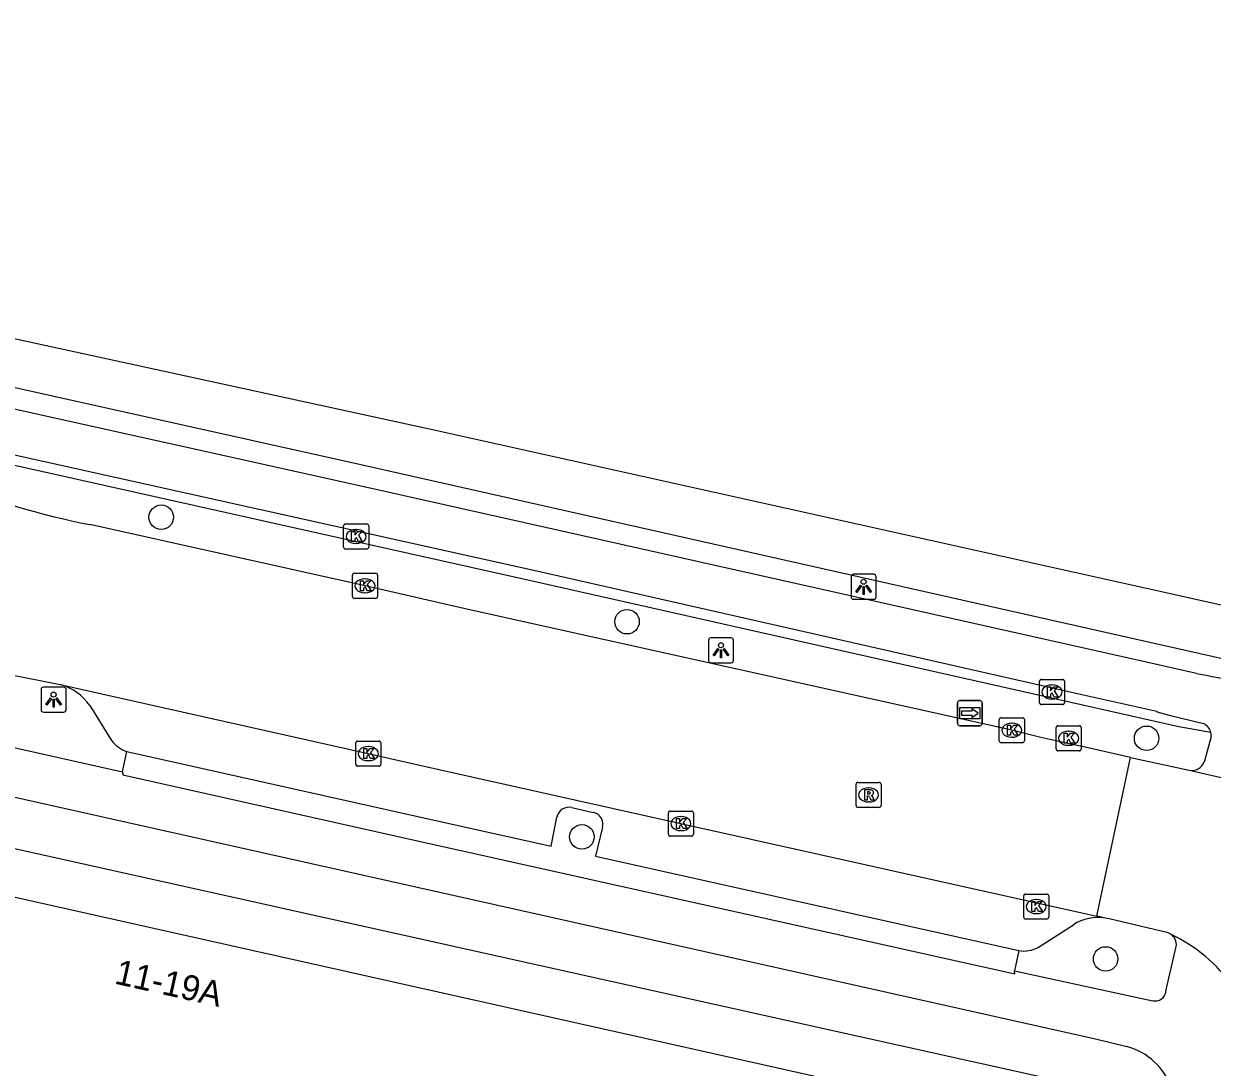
# Model space of a CAD drawing. Extents: x 161771 to 163125, y 382479 to 383177.
# Drawn here: x 162196.88 to 162244.33, y 383044.65 to 383086.29 of the extents above; entities that cross this region are included whole.
import ezdxf

# ---------------------------------------------------------------- set-up
doc = ezdxf.new("R2010")
doc.units = 0
for name, color, linetype in [('IMGEO_Boom', 7, 'Continuous'), ('IMGEO_Fietspad_gesloten', 7, 'Continuous'), ('IMGEO_Haag', 7, 'Continuous'), ('IMGEO_Kolk', 7, 'Continuous'), ('IMGEO_Lichtpunt', 7, 'Continuous'), ('IMGEO_Pand', 7, 'Continuous'), ('IMGEO_Pand_nummerreeks', 7, 'Continuous'), ('IMGEO_Parkeervlak_open', 7, 'Continuous'), ('IMGEO_Rijbaan_lokaal_gesloten', 7, 'Continuous'), ('IMGEO_Rijbaan_lokaal_open', 7, 'Continuous'), ('IMGEO_Rioolput', 7, 'Continuous'), ('IMGEO_Voetpad_open', 7, 'Continuous'), ('IMGEO_Wegwijzer', 7, 'Continuous')]:
    doc.layers.add(name, color=color, linetype=linetype)

msp = doc.modelspace()

# ---------------------------------------------------------------- linework, layer by layer
at = {"layer": 'IMGEO_Boom'}
for centre in [(162202.368, 383066.6), (162220.965, 383062.428), (162241.709, 383057.778), (162219.163, 383053.844), (162240.073, 383048.972)]:
    msp.add_circle(centre, 0.489, dxfattribs=at)
at = {"layer": 'IMGEO_Fietspad_gesloten'}
for points in [[(162243.707, 383060.368), (162241.754, 383060.795), (162210.53, 383067.797), (162194.926, 383071.263), (162193.872, 383071.53)], [(162195.294, 383069.358), (162217.239, 383064.484), (162239.123, 383059.53), (162242.124, 383058.863), (162242.112, 383058.831), (162242.616, 383058.703), (162243.975, 383058.365)], [(162170.379, 383061.276), (162174.223, 383060.417), (162179.202, 383059.305), (162239.663, 383045.787), (162240.925, 383045.477)], [(162179.884, 383061.009), (162180.126, 383061.066), (162200.828, 383056.444)], [(162244.014, 383056.841), (162244.286, 383057.805)], [(162200.828, 383056.444), (162200.835, 383056.323), (162212.596, 383053.683), (162236.448, 383048.373), (162236.439, 383048.504)], [(162242.483, 383047.687), (162242.895, 383049.474)], [(162236.439, 383048.504), (162240.976, 383047.517), (162241.952, 383047.305)]]:
    msp.add_lwpolyline(points, dxfattribs=at)
for centre, radius, start, end in [((162252.874, 383104.047), 44.631, 258.1478, 264.5942), ((162243.759, 383057.878), 0.532, 13.4374, 66.0806), ((162243.776, 383057.88), 0.516, 351.5944, 13.6371), ((162243.5, 383057.043), 0.552, 259.9807, 338.5741), ((162242.384, 383049.533), 0.515, 353.4298, 56.4625), ((162242.048, 383047.732), 0.438, 257.3897, 354.0726), ((162240.222, 383042.932), 2.641, 19.775, 74.561)]:
    msp.add_arc(centre, radius, start, end, dxfattribs=at)
at = {"layer": 'IMGEO_Haag'}
msp.add_lwpolyline([(162244.277, 383058.002), (162242.994, 383058.238), (162217.128, 383064.054), (162195.189, 383068.951)], dxfattribs=at)
at = {"layer": 'IMGEO_Kolk'}
for p, q in [((162209.651, 383065.404), (162209.651, 383066.256)), ((162209.726, 383066.33), (162210.578, 383066.33)), ((162210.139, 383066.11), (162210.164, 383066.11)), ((162210.652, 383066.256), (162210.652, 383065.404)), ((162210.162, 383065.55), (162210.137, 383065.55)), ((162210.578, 383065.33), (162209.726, 383065.33)), ((162210.005, 383063.436), (162210.005, 383064.288)), ((162210.08, 383064.362), (162210.932, 383064.362)), ((162210.493, 383064.142), (162210.518, 383064.142)), ((162211.006, 383064.288), (162211.006, 383063.436)), ((162210.516, 383063.582), (162210.491, 383063.582)), ((162210.932, 383063.362), (162210.08, 383063.362)), ((162237.432, 383059.198), (162237.432, 383060.05)), ((162237.507, 383060.124), (162238.359, 383060.124)), ((162237.92, 383059.904), (162237.945, 383059.904)), ((162238.433, 383060.05), (162238.433, 383059.198)), ((162237.943, 383059.344), (162237.918, 383059.344)), ((162238.359, 383059.124), (162237.507, 383059.124)), ((162235.829, 383057.673), (162235.829, 383058.525)), ((162235.904, 383058.599), (162236.756, 383058.599)), ((162236.317, 383058.379), (162236.342, 383058.379)), ((162236.83, 383058.525), (162236.83, 383057.673)), ((162238.096, 383057.35), (162238.096, 383058.202)), ((162238.171, 383058.276), (162239.023, 383058.276)), ((162238.584, 383058.056), (162238.609, 383058.056)), ((162239.097, 383058.202), (162239.097, 383057.35)), ((162210.136, 383056.738), (162210.136, 383057.59)), ((162210.211, 383057.664), (162211.063, 383057.664)), ((162210.624, 383057.444), (162210.649, 383057.444)), ((162211.137, 383057.59), (162211.137, 383056.738)), ((162236.756, 383057.599), (162235.904, 383057.599)), ((162236.34, 383057.819), (162236.315, 383057.819)), ((162238.607, 383057.496), (162238.582, 383057.496)), ((162239.023, 383057.276), (162238.171, 383057.276)), ((162211.063, 383056.664), (162210.211, 383056.664)), ((162210.647, 383056.884), (162210.622, 383056.884)), ((162222.617, 383053.946), (162222.617, 383054.798)), ((162222.692, 383054.872), (162223.544, 383054.872)), ((162223.105, 383054.652), (162223.13, 383054.652)), ((162223.618, 383054.798), (162223.618, 383053.946)), ((162223.128, 383054.092), (162223.103, 383054.092)), ((162223.544, 383053.872), (162222.692, 383053.872)), ((162236.803, 383050.635), (162236.803, 383051.487)), ((162236.878, 383051.561), (162237.73, 383051.561)), ((162237.291, 383051.341), (162237.316, 383051.341)), ((162237.804, 383051.487), (162237.804, 383050.635)), ((162237.314, 383050.781), (162237.289, 383050.781)), ((162237.73, 383050.561), (162236.878, 383050.561))]:
    msp.add_line(p, q, dxfattribs=at)
for points in [[(162209.651, 383065.404), (162209.651, 383066.256)], [(162209.726, 383066.33), (162210.578, 383066.33)], [(162209.972, 383066.03), (162210.095, 383066.03), (162210.095, 383065.879), (162210.225, 383066.03), (162210.389, 383066.03), (162210.243, 383065.879), (162210.396, 383065.63), (162210.244, 383065.63), (162210.159, 383065.794), (162210.095, 383065.727), (162210.095, 383065.63), (162209.972, 383065.63), (162209.972, 383066.03)], [(162210.652, 383066.256), (162210.652, 383065.404)], [(162210.578, 383065.33), (162209.726, 383065.33)], [(162210.005, 383063.436), (162210.005, 383064.288)], [(162210.08, 383064.362), (162210.932, 383064.362)], [(162210.326, 383064.062), (162210.449, 383064.062), (162210.449, 383063.911), (162210.579, 383064.062), (162210.743, 383064.062), (162210.597, 383063.911), (162210.75, 383063.662), (162210.598, 383063.662), (162210.513, 383063.826), (162210.449, 383063.759), (162210.449, 383063.662), (162210.326, 383063.662), (162210.326, 383064.062)], [(162211.006, 383064.288), (162211.006, 383063.436)], [(162210.932, 383063.362), (162210.08, 383063.362)], [(162237.432, 383059.198), (162237.432, 383060.05)], [(162237.507, 383060.124), (162238.359, 383060.124)], [(162237.753, 383059.824), (162237.876, 383059.824), (162237.876, 383059.673), (162238.006, 383059.824), (162238.17, 383059.824), (162238.024, 383059.673), (162238.177, 383059.424), (162238.025, 383059.424), (162237.94, 383059.588), (162237.876, 383059.521), (162237.876, 383059.424), (162237.753, 383059.424), (162237.753, 383059.824)], [(162238.433, 383060.05), (162238.433, 383059.198)], [(162238.359, 383059.124), (162237.507, 383059.124)], [(162235.829, 383057.673), (162235.829, 383058.525)], [(162235.904, 383058.599), (162236.756, 383058.599)], [(162236.83, 383058.525), (162236.83, 383057.673)], [(162236.15, 383058.299), (162236.273, 383058.299), (162236.273, 383058.148), (162236.403, 383058.299), (162236.567, 383058.299), (162236.421, 383058.148), (162236.574, 383057.899), (162236.422, 383057.899), (162236.337, 383058.063), (162236.273, 383057.996), (162236.273, 383057.899), (162236.15, 383057.899), (162236.15, 383058.299)], [(162238.096, 383057.35), (162238.096, 383058.202)], [(162238.171, 383058.276), (162239.023, 383058.276)], [(162238.417, 383057.976), (162238.54, 383057.976), (162238.54, 383057.825), (162238.67, 383057.976), (162238.834, 383057.976), (162238.688, 383057.825), (162238.841, 383057.576), (162238.689, 383057.576), (162238.604, 383057.74), (162238.54, 383057.673), (162238.54, 383057.576), (162238.417, 383057.576), (162238.417, 383057.976)], [(162239.097, 383058.202), (162239.097, 383057.35)], [(162210.136, 383056.738), (162210.136, 383057.59)], [(162210.211, 383057.664), (162211.063, 383057.664)], [(162211.137, 383057.59), (162211.137, 383056.738)], [(162236.756, 383057.599), (162235.904, 383057.599)], [(162210.457, 383057.364), (162210.58, 383057.364), (162210.58, 383057.213), (162210.71, 383057.364), (162210.874, 383057.364), (162210.728, 383057.213), (162210.881, 383056.964), (162210.729, 383056.964), (162210.644, 383057.128), (162210.58, 383057.061), (162210.58, 383056.964), (162210.457, 383056.964), (162210.457, 383057.364)], [(162239.023, 383057.276), (162238.171, 383057.276)], [(162211.063, 383056.664), (162210.211, 383056.664)], [(162222.617, 383053.946), (162222.617, 383054.798)], [(162222.692, 383054.872), (162223.544, 383054.872)], [(162222.938, 383054.572), (162223.061, 383054.572), (162223.061, 383054.421), (162223.191, 383054.572), (162223.355, 383054.572), (162223.209, 383054.421), (162223.362, 383054.172), (162223.21, 383054.172), (162223.125, 383054.336), (162223.061, 383054.269), (162223.061, 383054.172), (162222.938, 383054.172), (162222.938, 383054.572)], [(162223.618, 383054.798), (162223.618, 383053.946)], [(162223.544, 383053.872), (162222.692, 383053.872)], [(162236.803, 383050.635), (162236.803, 383051.487)], [(162236.878, 383051.561), (162237.73, 383051.561)], [(162237.124, 383051.261), (162237.247, 383051.261), (162237.247, 383051.11), (162237.377, 383051.261), (162237.541, 383051.261), (162237.395, 383051.11), (162237.548, 383050.861), (162237.396, 383050.861), (162237.311, 383051.025), (162237.247, 383050.958), (162237.247, 383050.861), (162237.124, 383050.861), (162237.124, 383051.261)], [(162237.804, 383051.487), (162237.804, 383050.635)], [(162237.73, 383050.561), (162236.878, 383050.561)]]:
    msp.add_lwpolyline(points, dxfattribs=at)
for centre, start, end in [((162209.728, 383066.254), 91.552, 178.448), ((162209.728, 383066.254), 91.552, 178.448), ((162210.576, 383066.254), 1.552, 88.448), ((162210.576, 383066.254), 1.552, 88.448), ((162209.728, 383065.406), 181.552, 268.448), ((162209.728, 383065.406), 181.552, 268.448), ((162210.576, 383065.406), 271.552, 358.448), ((162210.576, 383065.406), 271.552, 358.448), ((162210.082, 383064.286), 91.552, 178.448), ((162210.082, 383064.286), 91.552, 178.448), ((162210.93, 383064.286), 1.552, 88.448), ((162210.93, 383064.286), 1.552, 88.448), ((162210.082, 383063.438), 181.552, 268.448), ((162210.082, 383063.438), 181.552, 268.448), ((162210.93, 383063.438), 271.552, 358.448), ((162210.93, 383063.438), 271.552, 358.448), ((162237.509, 383060.048), 91.552, 178.448), ((162237.509, 383060.048), 91.552, 178.448), ((162238.357, 383060.048), 1.552, 88.448), ((162238.357, 383060.048), 1.552, 88.448), ((162237.509, 383059.2), 181.552, 268.448), ((162237.509, 383059.2), 181.552, 268.448), ((162238.357, 383059.2), 271.552, 358.448), ((162238.357, 383059.2), 271.552, 358.448), ((162235.906, 383058.523), 91.552, 178.448), ((162235.906, 383058.523), 91.552, 178.448), ((162236.754, 383058.523), 1.552, 88.448), ((162236.754, 383058.523), 1.552, 88.448), ((162238.173, 383058.2), 91.552, 178.448), ((162238.173, 383058.2), 91.552, 178.448), ((162239.021, 383058.2), 1.552, 88.448), ((162239.021, 383058.2), 1.552, 88.448), ((162210.213, 383057.588), 91.552, 178.448), ((162210.213, 383057.588), 91.552, 178.448), ((162211.061, 383057.588), 1.552, 88.448), ((162211.061, 383057.588), 1.552, 88.448), ((162235.906, 383057.675), 181.552, 268.448), ((162235.906, 383057.675), 181.552, 268.448), ((162236.754, 383057.675), 271.552, 358.448), ((162236.754, 383057.675), 271.552, 358.448), ((162238.173, 383057.352), 181.552, 268.448), ((162238.173, 383057.352), 181.552, 268.448), ((162239.021, 383057.352), 271.552, 358.448), ((162239.021, 383057.352), 271.552, 358.448), ((162210.213, 383056.74), 181.552, 268.448), ((162210.213, 383056.74), 181.552, 268.448), ((162211.061, 383056.74), 271.552, 358.448), ((162211.061, 383056.74), 271.552, 358.448), ((162222.694, 383054.796), 91.552, 178.448), ((162222.694, 383054.796), 91.552, 178.448), ((162223.542, 383054.796), 1.552, 88.448), ((162223.542, 383054.796), 1.552, 88.448), ((162222.694, 383053.948), 181.552, 268.448), ((162222.694, 383053.948), 181.552, 268.448), ((162223.542, 383053.948), 271.552, 358.448), ((162223.542, 383053.948), 271.552, 358.448), ((162236.88, 383051.485), 91.552, 178.448), ((162236.88, 383051.485), 91.552, 178.448), ((162237.728, 383051.485), 1.552, 88.448), ((162237.728, 383051.485), 1.552, 88.448), ((162236.88, 383050.637), 181.552, 268.448), ((162236.88, 383050.637), 181.552, 268.448), ((162237.728, 383050.637), 271.552, 358.448), ((162237.728, 383050.637), 271.552, 358.448)]:
    msp.add_arc(centre, 0.0765, start, end, dxfattribs=at)
for centre, major_axis, ratio, start_param, end_param in [((162210.138, 383065.83), (-0.387, 0.002), 0.722429, 4.712389, 7.853982), ((162210.163, 383065.83), (-0.39, 0.002), 0.717154, 1.570796, 4.712389), ((162210.492, 383063.862), (-0.387, 0.002), 0.722429, 4.712389, 7.853982), ((162210.517, 383063.862), (-0.39, 0.002), 0.717154, 1.570796, 4.712389), ((162237.919, 383059.624), (-0.387, 0.002), 0.722429, 4.712389, 7.853982), ((162237.944, 383059.624), (-0.39, 0.002), 0.717154, 1.570796, 4.712389), ((162236.316, 383058.099), (-0.387, 0.002), 0.722429, 4.712389, 7.853982), ((162236.341, 383058.099), (-0.39, 0.002), 0.717154, 1.570796, 4.712389), ((162238.583, 383057.776), (-0.387, 0.002), 0.722429, 4.712389, 7.853982), ((162238.608, 383057.776), (-0.39, 0.002), 0.717154, 1.570796, 4.712389), ((162210.623, 383057.164), (-0.387, 0.002), 0.722429, 4.712389, 7.853982), ((162210.648, 383057.164), (-0.39, 0.002), 0.717154, 1.570796, 4.712389), ((162223.104, 383054.372), (-0.387, 0.002), 0.722429, 4.712389, 7.853982), ((162223.129, 383054.372), (-0.39, 0.002), 0.717154, 1.570796, 4.712389), ((162237.29, 383051.061), (-0.387, 0.002), 0.722429, 4.712389, 7.853982), ((162237.315, 383051.061), (-0.39, 0.002), 0.717154, 1.570796, 4.712389)]:
    msp.add_ellipse(centre, major_axis=major_axis, ratio=ratio, start_param=start_param, end_param=end_param, dxfattribs=at)
at = {"layer": 'IMGEO_Lichtpunt'}
for p, q in [((162229.911, 383064.225), (162229.911, 383063.418)), ((162229.911, 383064.225), (162229.911, 383063.418)), ((162230.813, 383064.32), (162230.005, 383064.32)), ((162230.813, 383064.32), (162230.005, 383064.32)), ((162230.907, 383063.418), (162230.907, 383064.225)), ((162230.907, 383063.418), (162230.907, 383064.225)), ((162230.005, 383063.324), (162230.813, 383063.324)), ((162230.005, 383063.324), (162230.813, 383063.324)), ((162224.219, 383061.691), (162224.219, 383060.884)), ((162224.219, 383061.691), (162224.219, 383060.884)), ((162225.121, 383061.786), (162224.313, 383061.786)), ((162225.121, 383061.786), (162224.313, 383061.786)), ((162225.215, 383060.884), (162225.215, 383061.691)), ((162225.215, 383060.884), (162225.215, 383061.691)), ((162224.313, 383060.79), (162225.121, 383060.79)), ((162224.313, 383060.79), (162225.121, 383060.79)), ((162198.476, 383059.817), (162197.668, 383059.817)), ((162198.476, 383059.817), (162197.668, 383059.817)), ((162197.574, 383059.722), (162197.574, 383058.915)), ((162197.574, 383059.722), (162197.574, 383058.915)), ((162198.57, 383058.915), (162198.57, 383059.722)), ((162198.57, 383058.915), (162198.57, 383059.722)), ((162197.668, 383058.821), (162198.476, 383058.821)), ((162197.668, 383058.821), (162198.476, 383058.821))]:
    msp.add_line(p, q, dxfattribs=at)
for points in [[(162230.285, 383063.889), (162230.324, 383063.861), (162230.136, 383063.599), (162230.098, 383063.626), (162230.285, 383063.889)], [(162230.387, 383063.841), (162230.434, 383063.841), (162230.434, 383063.519), (162230.387, 383063.519), (162230.387, 383063.841)], [(162230.497, 383063.861), (162230.535, 383063.888), (162230.722, 383063.626), (162230.683, 383063.598), (162230.497, 383063.861)], [(162224.593, 383061.355), (162224.632, 383061.327), (162224.444, 383061.065), (162224.406, 383061.092), (162224.593, 383061.355)], [(162224.695, 383061.307), (162224.742, 383061.307), (162224.742, 383060.985), (162224.695, 383060.985), (162224.695, 383061.307)], [(162224.805, 383061.327), (162224.843, 383061.354), (162225.03, 383061.092), (162224.991, 383061.064), (162224.805, 383061.327)], [(162197.948, 383059.386), (162197.987, 383059.358), (162197.799, 383059.096), (162197.761, 383059.123), (162197.948, 383059.386)], [(162198.05, 383059.338), (162198.097, 383059.338), (162198.097, 383059.016), (162198.05, 383059.016), (162198.05, 383059.338)], [(162198.16, 383059.358), (162198.198, 383059.385), (162198.385, 383059.123), (162198.346, 383059.095), (162198.16, 383059.358)]]:
    msp.add_lwpolyline(points, dxfattribs=at)
for centre in [(162230.41, 383064.023), (162224.718, 383061.489), (162198.073, 383059.52)]:
    msp.add_circle(centre, 0.0994, dxfattribs=at)
for centre, start, end in [((162230.005, 383064.225), 90, 180), ((162230.005, 383064.225), 90, 180), ((162230.813, 383064.225), 0, 90), ((162230.813, 383064.225), 0, 90), ((162230.005, 383063.418), 180, 270), ((162230.005, 383063.418), 180, 270), ((162230.813, 383063.418), 270, 0), ((162230.813, 383063.418), 270, 360), ((162224.313, 383061.691), 90, 180), ((162224.313, 383061.691), 90, 180), ((162225.121, 383061.691), 0, 90), ((162225.121, 383061.691), 0, 90), ((162224.313, 383060.884), 180, 270), ((162224.313, 383060.884), 180, 270), ((162225.121, 383060.884), 270, 0), ((162225.121, 383060.884), 270, 360), ((162197.668, 383059.722), 90, 180), ((162197.668, 383059.722), 90, 180), ((162198.476, 383059.722), 0, 90), ((162198.476, 383059.722), 0, 90), ((162197.668, 383058.915), 180, 270), ((162197.668, 383058.915), 180, 270), ((162198.476, 383058.915), 270, 0), ((162198.476, 383058.915), 270, 360)]:
    msp.add_arc(centre, 0.0946, start, end, dxfattribs=at)
at = {"layer": 'IMGEO_Pand'}
msp.add_lwpolyline([(162177.897, 383057.502), (162177.562, 383055.68), (162228.166, 383044.363), (162236.101, 383042.589)], dxfattribs=at)
at = {"layer": 'IMGEO_Parkeervlak_open'}
for points in [[(162199.516, 383059.082), (162200.387, 383057.686)], [(162237.391, 383049.442), (162238.784, 383050.335)]]:
    msp.add_lwpolyline(points, dxfattribs=at)
for centre, radius, start, end in [((162197.771, 383057.881), 2.118, 34.5445, 74.5913), ((162201.353, 383058.388), 1.194, 216.0123, 252.8594), ((162239.758, 383048.857), 1.77, 79.8051, 123.3792), ((162236.826, 383050.404), 1.116, 258.9079, 300.4453)]:
    msp.add_arc(centre, radius, start, end, dxfattribs=at)
at = {"layer": 'IMGEO_Rijbaan_lokaal_gesloten'}
for points in [[(162241.065, 383057.014), (162239.137, 383057.449), (162238.689, 383057.548), (162237.487, 383057.812), (162236.33, 383058.099), (162214.628, 383062.922), (162210.506, 383063.862), (162199.522, 383066.303)], [(162180.732, 383063.217), (162184.012, 383062.631), (162185.456, 383062.396), (162186.972, 383062.124), (162189.574, 383061.583), (162193.841, 383060.81), (162198.334, 383059.923)], [(162198.334, 383059.923), (162210.633, 383057.165), (162213.395, 383056.54), (162223.114, 383054.374), (162239.727, 383050.676)], [(162239.727, 383050.676), (162241.065, 383057.014)]]:
    msp.add_lwpolyline(points, dxfattribs=at)
msp.add_arc((162205.89, 383098.374), 32.697, 248.1724, 258.769, dxfattribs=at)
at = {"layer": 'IMGEO_Rijbaan_lokaal_open'}
for points in [[(162241.065, 383057.014), (162243.404, 383056.499)], [(162243.404, 383056.499), (162246.891, 383055.711)], [(162240.071, 383050.599), (162239.727, 383050.676)], [(162242.516, 383050.031), (162240.217, 383050.567), (162240.071, 383050.599)]]:
    msp.add_lwpolyline(points, dxfattribs=at)
for centre, radius, start, end in [((162242.447, 383049.738), 0.301, 67.0028, 76.8304), ((162242.415, 383049.598), 0.443, 55.2666, 70.2761), ((162239.942, 383044.187), 6.386, 35.3051, 64.7264)]:
    msp.add_arc(centre, radius, start, end, dxfattribs=at)
at = {"layer": 'IMGEO_Rioolput'}
for p, q in [((162230.184, 383056.016), (162231.036, 383056.016)), ((162230.109, 383055.09), (162230.109, 383055.942)), ((162230.597, 383055.796), (162230.622, 383055.796)), ((162231.11, 383055.942), (162231.11, 383055.09)), ((162231.036, 383055.016), (162230.184, 383055.016)), ((162230.62, 383055.236), (162230.595, 383055.236))]:
    msp.add_line(p, q, dxfattribs=at)
for points in [[(162230.184, 383056.016), (162231.036, 383056.016)], [(162230.109, 383055.09), (162230.109, 383055.942)], [(162230.698, 383055.714), (162230.446, 383055.716), (162230.446, 383055.316)], [(162230.446, 383055.316), (162230.57, 383055.316), (162230.57, 383055.478), (162230.581, 383055.478)], [(162230.624, 383055.635), (162230.57, 383055.635), (162230.57, 383055.554)], [(162230.57, 383055.554), (162230.622, 383055.554)], [(162231.11, 383055.942), (162231.11, 383055.09)], [(162231.036, 383055.016), (162230.184, 383055.016)], [(162230.628, 383055.449), (162230.699, 383055.316), (162230.839, 383055.316), (162230.774, 383055.442)]]:
    msp.add_lwpolyline(points, dxfattribs=at)
for centre, radius, start, end in [((162230.186, 383055.94), 0.0765, 91.552, 178.448), ((162230.186, 383055.94), 0.0765, 91.552, 178.448), ((162231.034, 383055.94), 0.0765, 1.552, 88.448), ((162231.034, 383055.94), 0.0765, 1.552, 88.448), ((162230.58, 383055.425), 0.0533, 26.0293, 88.6989), ((162230.606, 383055.743), 0.19, 274.7715, 282.9687), ((162230.63, 383055.539), 0.0964, 77.0061, 93.1865), ((162230.644, 383055.596), 0.0378, 276.6634, 79.6772), ((162230.697, 383055.604), 0.109, 350.3612, 89.416), ((162230.695, 383055.604), 0.112, 277.5842, 350.9817), ((162230.679, 383055.389), 0.108, 29.5134, 73.7905), ((162230.186, 383055.092), 0.0765, 181.552, 268.448), ((162230.186, 383055.092), 0.0765, 181.552, 268.448), ((162231.034, 383055.092), 0.0765, 271.552, 358.448), ((162231.034, 383055.092), 0.0765, 271.552, 358.448)]:
    msp.add_arc(centre, radius, start, end, dxfattribs=at)
for centre, major_axis, ratio, start_param, end_param in [((162230.596, 383055.516), (-0.387, 0.002), 0.722429, 4.712389, 7.853982), ((162230.621, 383055.516), (-0.39, 0.002), 0.717154, 1.570796, 4.712389)]:
    msp.add_ellipse(centre, major_axis=major_axis, ratio=ratio, start_param=start_param, end_param=end_param, dxfattribs=at)
at = {"layer": 'IMGEO_Voetpad_open'}
for points in [[(162176.183, 383086.29), (162177.218, 383086.064), (162180.136, 383085.426), (162180.434, 383085.375), (162180.374, 383084.982), (162180.177, 383083.93), (162179.517, 383080.402), (162186.526, 383078.884), (162190.434, 383075.053), (162213.083, 383070.131), (162242.428, 383063.603), (162250.097, 383061.898)], [(162249.267, 383059.561), (162249.341, 383059.904), (162209.919, 383068.785), (162194.009, 383072.316), (162193.872, 383071.53)], [(162242.054, 383043.244), (162238.25, 383044.089), (162228.586, 383046.238), (162177.897, 383057.502)], [(162200.828, 383056.444), (162201.001, 383057.247)], [(162201.001, 383057.247), (162212.727, 383054.628), (162217.931, 383053.469), (162218.165, 383054.625)], [(162218.757, 383055.015), (162219.61, 383054.812)], [(162219.983, 383054.224), (162219.703, 383053.073), (162236.611, 383049.309)], [(162236.611, 383049.309), (162236.439, 383048.504)]]:
    msp.add_lwpolyline(points, dxfattribs=at)
for centre, radius, start, end in [((162218.651, 383054.532), 0.495, 77.6403, 169.1121), ((162219.549, 383054.361), 0.455, 342.52, 82.2583)]:
    msp.add_arc(centre, radius, start, end, dxfattribs=at)
at = {"layer": 'IMGEO_Wegwijzer'}
for p, q in [((162234.258, 383059.279), (162235.048, 383059.279)), ((162235.048, 383059.279), (162234.258, 383059.279)), ((162234.158, 383058.379), (162234.158, 383059.179)), ((162234.158, 383059.179), (162234.158, 383058.379)), ((162235.148, 383059.179), (162235.148, 383058.379)), ((162235.148, 383058.379), (162235.148, 383059.179)), ((162235.048, 383058.279), (162234.258, 383058.279)), ((162234.258, 383058.279), (162235.048, 383058.279))]:
    msp.add_line(p, q, dxfattribs=at)
for points in [[(162234.259, 383059.011), (162235.047, 383059.011), (162235.047, 383058.547), (162234.259, 383058.547), (162234.259, 383059.011)], [(162234.324, 383058.863), (162234.324, 383058.779), (162234.324, 383058.695), (162234.735, 383058.695), (162234.735, 383058.612), (162234.982, 383058.779), (162234.735, 383058.946), (162234.735, 383058.863), (162234.324, 383058.863)]]:
    msp.add_lwpolyline(points, dxfattribs=at)
for centre, start, end in [((162234.258, 383059.179), 90, 180), ((162234.258, 383059.179), 90, 180), ((162235.048, 383059.179), 0, 90), ((162235.048, 383059.179), 360, 90), ((162234.258, 383058.379), 180, 270), ((162234.258, 383058.379), 180, 270), ((162235.048, 383058.379), 270, 0), ((162235.048, 383058.379), 270, 0)]:
    msp.add_arc(centre, 0.1, start, end, dxfattribs=at)

# ---------------------------------------------------------------- texts
at = {"layer": 'IMGEO_Pand_nummerreeks'}
msp.add_text('11-19A', height=1, rotation=347.3939, dxfattribs=at).set_placement((162200.465, 383047.996))

doc.saveas('drawing.dxf')
